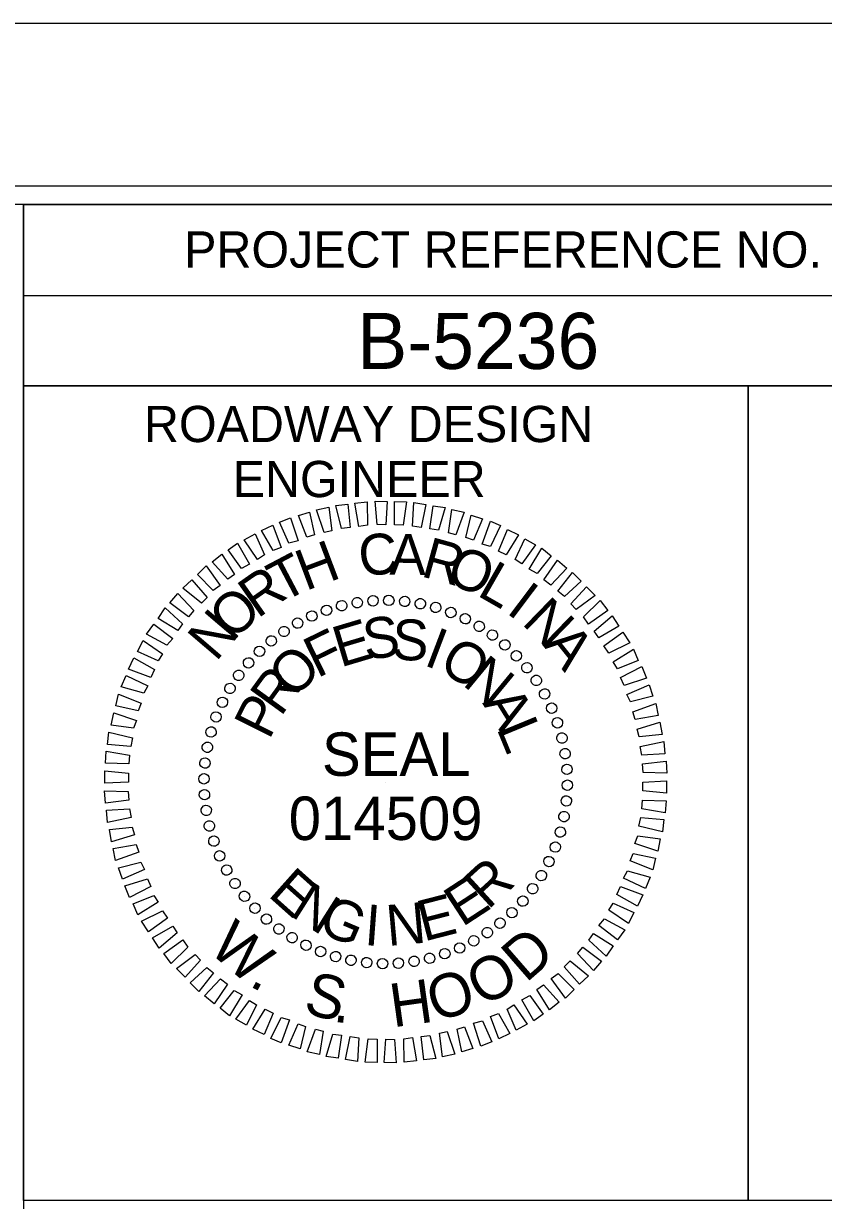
# Model space of a CAD drawing. Extents: x 575424 to 577182, y -52702 to -51602.
# Drawn here: x 576965.2 to 577075.6, y -51765 to -51602.5 of the extents above; entities that cross this region are included whole.
import ezdxf

# ---------------------------------------------------------------- set-up
doc = ezdxf.new("R2010")
doc.units = 0
for name, color, linetype in [('Sheet Cutting Line CELL', 7, 'Continuous'), ('Sheet Data Field CELL', 7, 'Continuous'), ('Sheet PE Seal Cell', 7, 'Continuous'), ('Sheet Plot Border Inside CELL', 7, 'Continuous'), ('Sheet Plot Border Outside CELL', 7, 'Continuous'), ('Sheet Profile CELL', 7, 'Continuous'), ('Sheet Profile Grid Major CELL', 7, 'Continuous'), ('Typical Detail Wedge2 CELL', 7, 'Continuous')]:
    doc.layers.add(name, color=color, linetype=linetype)

msp = doc.modelspace()

# ---------------------------------------------------------------- linework, layer by layer
at = {"layer": 'Sheet Cutting Line CELL'}
msp.add_line((577182.21, -51602.49), (575498.21, -51602.49), dxfattribs=at)
at = {"layer": 'Sheet PE Seal Cell'}
for p, q in [((577009.08, -51682.88), (577009.08, -51682.88)), ((577011.28, -51682.48), (577011.28, -51682.48)), ((577013.43, -51682.18), (577013.43, -51682.18)), ((577015.63, -51682.13), (577015.63, -51682.13)), ((577017.83, -51682.28), (577017.83, -51682.28)), ((577019.98, -51682.63), (577019.98, -51682.63)), ((577004.98, -51684.28), (577004.98, -51684.28)), ((577006.98, -51683.48), (577006.98, -51683.48)), ((577022.08, -51683.08), (577022.08, -51683.08)), ((577024.18, -51683.78), (577024.18, -51683.78)), ((577003.03, -51685.28), (577003.03, -51685.28)), ((577026.18, -51684.68), (577026.18, -51684.68)), ((577028.13, -51685.68), (577028.13, -51685.68)), ((576999.38, -51687.68), (576999.38, -51687.68)), ((577001.13, -51686.43), (577001.13, -51686.43)), ((577029.93, -51686.93), (577029.93, -51686.93)), ((576997.73, -51689.18), (576997.73, -51689.18)), ((577031.68, -51688.28), (577031.68, -51688.28)), ((576996.23, -51690.73), (576996.23, -51690.73)), ((577033.23, -51689.78), (577033.23, -51689.78)), ((576994.88, -51692.48), (576994.88, -51692.48)), ((577034.73, -51691.43), (577034.73, -51691.43)), ((576993.63, -51694.28), (576993.63, -51694.28)), ((577035.98, -51693.18), (577035.98, -51693.18)), ((577037.13, -51695.08), (577037.13, -51695.08)), ((576992.63, -51696.23), (576992.63, -51696.23)), ((577038.13, -51697.03), (577038.13, -51697.03)), ((576991.73, -51698.23), (576991.73, -51698.23)), ((577038.93, -51699.03), (577038.93, -51699.03)), ((576991.03, -51700.33), (576991.03, -51700.33)), ((576990.58, -51702.43), (576990.58, -51702.43)), ((577039.53, -51701.13), (577039.53, -51701.13)), ((577039.93, -51703.33), (577039.93, -51703.33)), ((576990.23, -51704.58), (576990.23, -51704.58)), ((577040.23, -51705.48), (577040.23, -51705.48)), ((576990.08, -51706.78), (576990.08, -51706.78)), ((577015.18, -51707.23), (577015.18, -51707.23)), ((577040.28, -51707.68), (577040.28, -51707.68)), ((576990.13, -51708.98), (576990.13, -51708.98)), ((577040.13, -51709.88), (577040.13, -51709.88)), ((576990.43, -51711.13), (576990.43, -51711.13)), ((577039.78, -51712.03), (577039.78, -51712.03)), ((576990.83, -51713.33), (576990.83, -51713.33)), ((576991.43, -51715.43), (576991.43, -51715.43)), ((577039.33, -51714.13), (577039.33, -51714.13)), ((577038.63, -51716.23), (577038.63, -51716.23)), ((576992.23, -51717.43), (576992.23, -51717.43)), ((577037.73, -51718.23), (577037.73, -51718.23)), ((576993.23, -51719.38), (576993.23, -51719.38)), ((577036.73, -51720.18), (577036.73, -51720.18)), ((576994.38, -51721.28), (576994.38, -51721.28)), ((576995.63, -51723.03), (576995.63, -51723.03)), ((577035.48, -51721.98), (577035.48, -51721.98)), ((576997.13, -51724.68), (576997.13, -51724.68)), ((577034.13, -51723.73), (577034.13, -51723.73)), ((576998.68, -51726.18), (576998.68, -51726.18)), ((577030.98, -51726.78), (577030.98, -51726.78)), ((577032.63, -51725.28), (577032.63, -51725.28)), ((577000.43, -51727.53), (577000.43, -51727.53)), ((577029.23, -51728.03), (577029.23, -51728.03)), ((577002.23, -51728.78), (577002.23, -51728.78)), ((577004.18, -51729.78), (577004.18, -51729.78)), ((577027.33, -51729.18), (577027.33, -51729.18)), ((577006.18, -51730.68), (577006.18, -51730.68)), ((577008.28, -51731.38), (577008.28, -51731.38)), ((577021.28, -51731.58), (577021.28, -51731.58)), ((577023.38, -51730.98), (577023.38, -51730.98)), ((577025.38, -51730.18), (577025.38, -51730.18)), ((577010.38, -51731.83), (577010.38, -51731.83)), ((577012.53, -51732.18), (577012.53, -51732.18)), ((577014.73, -51732.33), (577014.73, -51732.33)), ((577016.93, -51732.28), (577016.93, -51732.28)), ((577019.08, -51731.98), (577019.08, -51731.98))]:
    msp.add_line(p, q, dxfattribs=at)
for points in [[(577006.68, -51672.78), (577005.63, -51669.63), (577007.33, -51669.28), (577007.73, -51672.53)], [(577009.08, -51672.23), (577008.28, -51669.03), (577009.93, -51668.88), (577010.28, -51672.08)], [(577011.48, -51671.93), (577010.93, -51668.73), (577012.63, -51668.53), (577012.68, -51671.78)], [(577013.98, -51671.68), (577013.73, -51668.43), (577015.38, -51668.48), (577015.18, -51671.73)], [(577016.38, -51671.73), (577016.38, -51668.48), (577018.03, -51668.53), (577017.58, -51671.78)], [(577018.88, -51671.88), (577019.08, -51668.63), (577020.73, -51668.93), (577020.08, -51672.08)], [(577021.28, -51672.28), (577021.73, -51669.08), (577023.38, -51669.33), (577022.48, -51672.43)], [(577023.83, -51672.83), (577024.33, -51669.58), (577026.03, -51669.98), (577024.88, -51673.08)], [(577001.83, -51674.23), (577000.53, -51671.33), (577002.03, -51670.73), (577003.08, -51673.93)], [(577004.28, -51673.43), (577003.13, -51670.43), (577004.68, -51669.98), (577005.33, -51673.08)], [(577026.23, -51673.48), (577026.98, -51670.38), (577028.53, -51670.88), (577027.28, -51673.83)], [(577028.48, -51674.38), (577029.63, -51671.23), (577031.03, -51671.83), (577029.63, -51674.73)], [(576997.48, -51676.48), (576995.63, -51673.78), (576997.18, -51672.98), (576998.43, -51675.88)], [(576999.63, -51675.28), (576998.03, -51672.48), (576999.58, -51671.78), (577000.73, -51674.83)], [(577030.73, -51675.33), (577031.98, -51672.38), (577033.53, -51673.08), (577031.83, -51675.88)], [(576995.28, -51677.73), (576993.43, -51675.18), (576994.73, -51674.23), (576996.38, -51677.13)], [(577033.03, -51676.48), (577034.38, -51673.63), (577035.88, -51674.48), (577033.98, -51677.08)], [(576993.38, -51679.23), (576991.23, -51676.83), (576992.58, -51675.78), (576994.33, -51678.58)], [(577034.98, -51677.83), (577036.73, -51674.93), (577038.03, -51675.98), (577036.08, -51678.43)], [(576991.38, -51680.78), (576989.18, -51678.58), (576990.38, -51677.38), (576992.33, -51680.08)], [(577037.03, -51679.33), (577038.88, -51676.58), (577040.18, -51677.68), (577037.98, -51680.03)], [(576989.73, -51682.53), (576987.18, -51680.48), (576988.43, -51679.33), (576990.53, -51681.73)], [(577038.93, -51680.88), (577040.98, -51678.28), (577042.18, -51679.48), (577039.88, -51681.63)], [(576987.98, -51684.43), (576985.38, -51682.48), (576986.48, -51681.18), (576988.68, -51683.53)], [(577040.73, -51682.63), (577042.88, -51680.28), (577044.08, -51681.48), (577041.48, -51683.43)], [(577042.48, -51684.43), (577044.78, -51682.18), (577045.83, -51683.53), (577043.18, -51685.43)], [(576986.48, -51686.33), (576983.78, -51684.63), (576984.73, -51683.18), (576987.13, -51685.38)], [(577043.98, -51686.38), (577046.43, -51684.28), (577047.38, -51685.73), (577044.58, -51687.33)], [(576984.98, -51688.33), (576982.18, -51686.83), (576983.18, -51685.43), (576985.78, -51687.43)], [(576983.78, -51690.48), (576980.93, -51689.23), (576981.68, -51687.68), (576984.38, -51689.53)], [(577045.28, -51688.43), (577047.93, -51686.53), (577048.88, -51688.03), (577045.98, -51689.43)], [(577046.58, -51690.63), (577049.38, -51688.88), (577050.03, -51690.43), (577047.18, -51691.58)], [(576982.78, -51692.78), (576979.68, -51691.63), (576980.43, -51690.08), (576983.28, -51691.68)], [(576981.78, -51694.98), (576978.68, -51694.08), (576979.33, -51692.53), (576982.33, -51693.93)], [(577047.58, -51692.78), (577050.53, -51691.28), (577051.18, -51692.88), (577048.08, -51693.88)], [(577048.48, -51695.13), (577051.53, -51693.83), (577052.08, -51695.38), (577048.98, -51696.18)], [(576981.03, -51697.38), (576977.93, -51696.73), (576978.28, -51695.08), (576981.43, -51696.33)], [(577049.28, -51697.53), (577052.48, -51696.38), (577052.78, -51698.03), (577049.63, -51698.58)], [(576980.38, -51699.78), (576977.28, -51699.38), (576977.63, -51697.68), (576980.78, -51698.73)], [(577049.88, -51699.93), (577053.03, -51698.98), (577053.33, -51700.68), (577050.18, -51700.98)], [(576979.98, -51702.33), (576976.78, -51702.03), (576976.98, -51700.33), (576980.23, -51701.13)], [(577050.33, -51702.33), (577053.58, -51701.63), (577053.73, -51703.33), (577050.53, -51703.53)], [(576979.73, -51704.73), (576976.48, -51704.63), (576976.58, -51702.98), (576979.83, -51703.53)], [(576979.68, -51707.23), (576976.43, -51707.38), (576976.43, -51705.68), (576979.68, -51706.03)], [(577050.63, -51704.73), (577053.88, -51704.33), (577053.98, -51706.03), (577050.73, -51705.93)], [(577050.68, -51707.23), (577053.93, -51707.08), (577053.93, -51708.78), (577050.68, -51708.43)], [(576979.73, -51709.73), (576976.48, -51710.13), (576976.38, -51708.43), (576979.63, -51708.53)], [(577050.63, -51709.73), (577053.88, -51709.83), (577053.78, -51711.48), (577050.53, -51710.93)], [(576980.03, -51712.13), (576976.78, -51712.83), (576976.63, -51711.13), (576979.83, -51710.93)], [(577050.38, -51712.13), (577053.58, -51712.43), (577053.38, -51714.13), (577050.13, -51713.33)], [(576980.48, -51714.53), (576977.33, -51715.48), (576977.03, -51713.78), (576980.18, -51713.48)], [(577049.98, -51714.68), (577053.08, -51715.08), (577052.73, -51716.78), (577049.58, -51715.73)], [(576981.08, -51716.93), (576977.88, -51718.08), (576977.58, -51716.43), (576980.73, -51715.88)], [(577049.33, -51717.08), (577052.43, -51717.73), (577052.08, -51719.38), (577048.93, -51718.13)], [(576981.88, -51719.33), (576978.83, -51720.63), (576978.28, -51719.08), (576981.38, -51718.28)], [(577048.58, -51719.48), (577051.68, -51720.38), (577051.03, -51721.93), (577048.03, -51720.53)], [(576982.78, -51721.68), (576979.83, -51723.18), (576979.18, -51721.58), (576982.28, -51720.58)], [(577047.58, -51721.68), (577050.68, -51722.83), (577049.93, -51724.38), (577047.08, -51722.78)], [(576983.78, -51723.83), (576980.98, -51725.58), (576980.33, -51724.03), (576983.18, -51722.88)], [(576985.08, -51726.03), (576982.43, -51727.93), (576981.48, -51726.43), (576984.38, -51725.03)], [(577046.58, -51723.98), (577049.43, -51725.23), (577048.68, -51726.78), (577045.98, -51724.93)], [(577045.38, -51726.13), (577048.18, -51727.63), (577047.18, -51729.03), (577044.58, -51727.03)], [(576986.38, -51728.08), (576983.93, -51730.18), (576982.98, -51728.73), (576985.78, -51727.13)], [(577043.88, -51728.13), (577046.58, -51729.83), (577045.63, -51731.28), (577043.23, -51729.08)], [(576987.88, -51730.03), (576985.58, -51732.28), (576984.53, -51730.93), (576987.18, -51729.03)], [(577042.38, -51730.03), (577044.98, -51731.98), (577043.88, -51733.28), (577041.68, -51730.93)], [(576989.63, -51731.83), (576987.48, -51734.18), (576986.28, -51732.98), (576988.88, -51731.03)], [(576991.43, -51733.58), (576989.38, -51736.18), (576988.18, -51734.98), (576990.48, -51732.83)], [(577040.63, -51731.93), (577043.18, -51733.98), (577041.93, -51735.13), (577039.83, -51732.73)], [(576993.33, -51735.13), (576991.48, -51737.88), (576990.18, -51736.78), (576992.38, -51734.43)], [(577038.98, -51733.68), (577041.18, -51735.88), (577039.98, -51737.08), (577038.03, -51734.38)], [(576995.38, -51736.63), (576993.63, -51739.53), (576992.33, -51738.48), (576994.28, -51736.03)], [(577036.98, -51735.23), (577039.13, -51737.63), (577037.78, -51738.68), (577036.03, -51735.88)], [(576997.33, -51737.98), (576995.98, -51740.83), (576994.48, -51739.98), (576996.38, -51737.38)], [(577032.88, -51737.98), (577034.73, -51740.68), (577033.18, -51741.48), (577031.93, -51738.58)], [(577035.08, -51736.73), (577036.93, -51739.28), (577035.63, -51740.23), (577033.98, -51737.33)], [(576999.63, -51739.13), (576998.38, -51742.08), (576996.83, -51741.38), (576998.53, -51738.58)], [(577001.88, -51740.08), (577000.73, -51743.23), (576999.33, -51742.63), (577000.73, -51739.73)], [(577030.73, -51739.18), (577032.33, -51741.98), (577030.78, -51742.68), (577029.63, -51739.63)], [(577004.13, -51740.98), (577003.38, -51744.08), (577001.83, -51743.58), (577003.08, -51740.63)], [(577006.53, -51741.63), (577006.03, -51744.88), (577004.33, -51744.48), (577005.48, -51741.38)], [(577026.08, -51741.03), (577027.23, -51744.03), (577025.68, -51744.48), (577025.03, -51741.38)], [(577028.53, -51740.23), (577029.83, -51743.13), (577028.33, -51743.73), (577027.28, -51740.53)], [(577009.08, -51742.18), (577008.63, -51745.38), (577006.98, -51745.13), (577007.88, -51742.03)], [(577011.48, -51742.58), (577011.28, -51745.83), (577009.63, -51745.53), (577010.28, -51742.38)], [(577013.98, -51742.73), (577013.98, -51745.98), (577012.33, -51745.93), (577012.78, -51742.68)], [(577016.38, -51742.78), (577016.63, -51746.03), (577014.98, -51745.98), (577015.18, -51742.73)], [(577018.88, -51742.53), (577019.43, -51745.73), (577017.73, -51745.93), (577017.68, -51742.68)], [(577021.28, -51742.23), (577022.08, -51745.43), (577020.43, -51745.58), (577020.08, -51742.38)], [(577023.68, -51741.68), (577024.73, -51744.83), (577023.03, -51745.18), (577022.63, -51741.93)]]:
    msp.add_lwpolyline(points, close=True, dxfattribs=at)
for centre, major_axis in [((577007.01, -51683.52), (-0.234, 0.681)), ((577009.11, -51682.89), (-0.174, 0.699)), ((577011.25, -51682.46), (-0.113, 0.711)), ((577013.43, -51682.21), (-0.05, 0.718)), ((577015.61, -51682.15), (0.013, 0.72)), ((577017.8, -51682.29), (0.075, 0.716)), ((577019.96, -51682.61), (0.137, 0.707)), ((577022.09, -51683.12), (0.198, 0.692)), ((577003.02, -51685.29), (-0.349, 0.63)), ((577004.98, -51684.32), (-0.293, 0.658)), ((577024.17, -51683.82), (0.258, 0.672)), ((577026.17, -51684.69), (0.316, 0.647)), ((577001.15, -51686.44), (-0.403, 0.597)), ((577028.09, -51685.73), (0.371, 0.617)), ((577029.92, -51686.94), (0.423, 0.582)), ((576999.39, -51687.74), (-0.453, 0.56)), ((577031.63, -51688.3), (0.472, 0.543)), ((576997.76, -51689.19), (-0.5, 0.518)), ((577033.22, -51689.81), (0.518, 0.5)), ((576996.25, -51690.78), (-0.543, 0.472)), ((577034.67, -51691.45), (0.56, 0.453)), ((576994.89, -51692.49), (-0.582, 0.423)), ((577035.97, -51693.2), (0.597, 0.403)), ((576993.68, -51694.31), (-0.617, 0.371)), ((577037.11, -51695.07), (0.63, 0.349)), ((576992.64, -51696.23), (-0.647, 0.316)), ((576991.76, -51698.24), (-0.672, 0.258)), ((577038.09, -51697.03), (0.658, 0.293)), ((577038.89, -51699.06), (0.681, 0.234)), ((576991.07, -51700.32), (-0.692, 0.198)), ((577039.51, -51701.16), (0.699, 0.174)), ((576990.56, -51702.44), (-0.707, 0.137)), ((576990.23, -51704.61), (-0.716, 0.075)), ((577039.95, -51703.31), (0.711, 0.113)), ((577040.2, -51705.48), (0.718, 0.05)), ((576990.1, -51706.79), (-0.72, 0.013)), ((577040.25, -51707.67), (0.72, -0.013)), ((576990.16, -51708.98), (-0.718, -0.05)), ((576990.41, -51711.15), (-0.711, -0.113)), ((577040.12, -51709.85), (0.716, -0.075)), ((577039.8, -51712.01), (0.707, -0.137)), ((576990.84, -51713.3), (-0.699, -0.174)), ((577039.29, -51714.14), (0.692, -0.198)), ((576991.46, -51715.39), (-0.681, -0.234)), ((577038.59, -51716.22), (0.672, -0.258)), ((576992.27, -51717.43), (-0.658, -0.293)), ((576993.24, -51719.39), (-0.63, -0.349)), ((577037.72, -51718.22), (0.647, -0.316)), ((577036.67, -51720.15), (0.617, -0.371)), ((576994.38, -51721.25), (-0.597, -0.403)), ((577035.47, -51721.97), (0.582, -0.423)), ((576995.69, -51723.01), (-0.56, -0.453)), ((577034.11, -51723.68), (0.543, -0.472)), ((576997.14, -51724.65), (-0.518, -0.5)), ((577032.6, -51725.27), (0.5, -0.518)), ((576998.72, -51726.16), (-0.472, -0.543)), ((577000.44, -51727.52), (-0.423, -0.582)), ((577030.96, -51726.72), (0.453, -0.56)), ((577002.26, -51728.73), (-0.371, -0.617)), ((577027.34, -51729.16), (0.349, -0.63)), ((577029.2, -51728.02), (0.403, -0.597)), ((577004.18, -51729.77), (-0.316, -0.647)), ((577006.19, -51730.64), (-0.258, -0.672)), ((577025.38, -51730.14), (0.293, -0.658)), ((577008.26, -51731.34), (-0.198, -0.692)), ((577010.39, -51731.85), (-0.137, -0.707)), ((577012.56, -51732.17), (-0.075, -0.716)), ((577014.74, -51732.31), (-0.013, -0.72)), ((577016.93, -51732.25), (0.05, -0.718)), ((577019.1, -51732), (0.113, -0.711)), ((577021.24, -51731.56), (0.174, -0.699)), ((577023.34, -51730.94), (0.234, -0.681))]:
    msp.add_ellipse(centre, major_axis=major_axis, ratio=0.999708, dxfattribs=at)
at = {"layer": 'Sheet Plot Border Inside CELL'}
msp.add_lwpolyline([(577177.71, -51624.94), (575511.21, -51624.94), (575511.21, -52680.04), (577177.71, -52680.04)], close=True, dxfattribs=at)
at = {"layer": 'Sheet Plot Border Outside CELL'}
msp.add_lwpolyline([(577182.21, -51602.49), (575498.21, -51602.49), (575498.21, -52702.49), (577182.21, -52702.49)], close=True, dxfattribs=at)
at = {"layer": 'Sheet Profile CELL'}
for p, q in [((576965.16, -51640.04), (577165.21, -51640.04)), ((577065.21, -51652.54), (577065.21, -51764.99))]:
    msp.add_line(p, q, dxfattribs=at)
for points in [[(577165.21, -51627.49), (575665.21, -51627.49), (575665.21, -52677.49), (577165.21, -52677.49)], [(576965.16, -51627.49), (577165.21, -51627.49), (577165.21, -51652.54), (576965.16, -51652.54)], [(576965.16, -51652.54), (577065.21, -51652.54), (577065.21, -51765.04), (576965.16, -51765.04)], [(577065.21, -51652.54), (577165.21, -51652.54), (577165.21, -51765.04), (577065.21, -51765.04)]]:
    msp.add_lwpolyline(points, close=True, dxfattribs=at)
at = {"layer": 'Sheet Profile Grid Major CELL'}
msp.add_lwpolyline([(576965.21, -52652.49), (576965.21, -51627.49), (576991.51, -51627.49)], dxfattribs=at)

# ---------------------------------------------------------------- texts
at = {"layer": 'Sheet Data Field CELL'}
msp.add_text('B-5236', height=7.75, dxfattribs=at).set_placement((577011.24, -51650.19))
at = {"layer": 'Sheet PE Seal Cell'}
for s, height, rotation, p in [('C', 5.64, 6.2199, (577011.73, -51678.88)), ('A', 5.64, 359.0203, (577015.68, -51678.58)), ('H', 5.64, 20.6195, (577004.13, -51680.88)), ('R', 5.64, 344.6211, (577019.88, -51678.78)), ('T', 5.64, 27.8198, (577000.88, -51682.53)), ('O', 5.64, 337.4212, (577023.23, -51679.53)), ('R', 5.64, 35.0205, (576997.48, -51684.73)), ('L', 5.64, 330.2209, (577027.63, -51681.38)), ('I', 5.64, 323.0201, (577031.68, -51683.78)), ('O', 5.64, 42.2217, (576994.03, -51687.83)), ('N', 5.64, 315.8189, (577033.83, -51685.33)), ('N', 5.64, 49.4235, (576991.73, -51690.73)), ('S', 5.64, 7.2556, (577012.38, -51690.38)), ('F', 5.64, 25.967, (577005.73, -51692.93)), ('E', 5.64, 16.6111, (577008.93, -51691.43)), ('S', 5.64, 357.9004, (577015.98, -51690.33)), ('I', 5.64, 339.1896, (577020.28, -51691.03)), ('O', 5.64, 329.8335, (577022.28, -51691.73)), ('A', 5.64, 308.6172, (577036.78, -51688.28)), ('O', 5.64, 44.6812, (577002.43, -51695.88)), ('N', 5.64, 320.4766, (577025.63, -51693.73)), ('R', 5.64, 54.0397, (577000.68, -51698.33)), ('P', 5.64, 63.3989, (576999.08, -51701.53)), ('A', 5.64, 301.7603, (577028.48, -51696.33)), ('L', 5.64, 292.4008, (577030.43, -51699.78)), ('SEAL', 5.998, 360, (577006.38, -51706.38)), ('R', 5.64, 42.4814, (577029.28, -51724.98)), ('E', 5.64, 318.2769, (576998.78, -51722.88)), ('E', 5.64, 33.1241, (577025.73, -51727.33)), ('N', 5.64, 327.634, (577001.78, -51725.58)), ('G', 5.64, 336.9902, (577005.58, -51727.83)), ('E', 5.64, 14.4118, (577020.43, -51729.28)), ('I', 5.64, 355.7012, (577012.13, -51729.73)), ('N', 5.64, 5.0564, (577015.48, -51729.88))]:
    msp.add_text(s, height=height, rotation=rotation, dxfattribs=at).set_placement(p)
msp.add_text('014509', height=5.998, dxfattribs=at).set_placement((577001.79, -51715.24))
at = {"layer": 'Sheet Profile CELL'}
for s, height, p in [('PROJECT REFERENCE NO.', 5.0001, (576987.36, -51636.19)), ('ROADWAY DESIGN', 5.0001, (576981.81, -51660.29)), ('ENGINEER', 5, (576994.06, -51667.89))]:
    msp.add_text(s, height=height, dxfattribs=at).set_placement(p)
at = {"layer": 'Typical Detail Wedge2 CELL'}
for s, rotation, p in [('W', 319.62, (576990.54, -51730.51)), ('D', 41.0529, (577034.53, -51735.06)), ('O', 29.4925, (577028.56, -51738.38)), ('.', 332.1541, (576996.18, -51735.31)), ('S', 346.3882, (577003.66, -51739.12)), ('H', 7.9481, (577016.19, -51741.12)), ('O', 17.9321, (577022.05, -51740.43)), ('.', 353.7139, (577007.82, -51740.32))]:
    msp.add_text(s, height=6, rotation=rotation, dxfattribs=at).set_placement(p)

doc.saveas('drawing.dxf')
